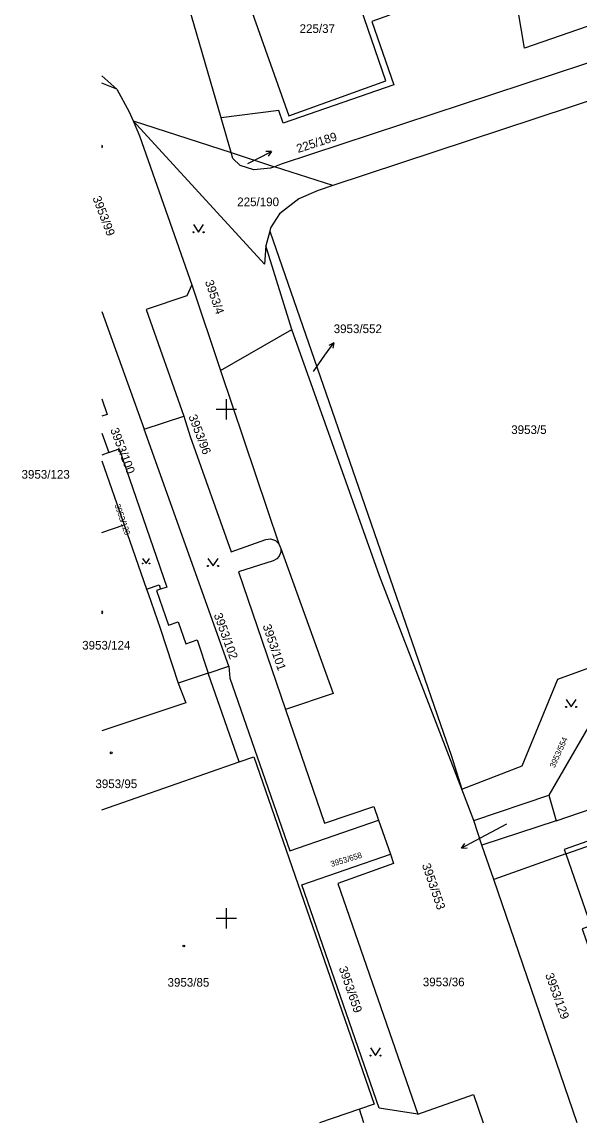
# Model space of a CAD drawing. Extents: x -599970 to -599524, y -1154772 to -1154457.
# Drawn here: x -599970.1 to -599915.3, y -1154770.1 to -1154661.9 of the extents above; entities that cross this region are included whole.
import ezdxf

# ---------------------------------------------------------------- set-up
doc = ezdxf.new("R2010")
doc.units = 0
doc.layers.add('Z-KATASTRALNI MAPA', color=7, linetype='Continuous')
doc.layers.add('Z-KRIZKY CTVERCOVE SITE', color=7, linetype='Continuous')

msp = doc.modelspace()

# ---------------------------------------------------------------- linework, layer by layer
at = {"layer": 'Z-KATASTRALNI MAPA'}
for p, q in [((-599934.32, -1154667.72), (-599940.18, -1154650.81)), ((-599950.09, -1154653.66), (-599943.86, -1154671.15)), ((-599950.53, -1154671.34), (-599955.15, -1154655.41)), ((-599960.77, -1154668.53), (-599962.24, -1154667.94)), ((-599943.86, -1154671.15), (-599934.32, -1154667.72)), ((-599912.85, -1154669.18), (-599939.53, -1154678.01)), ((-599946.25, -1154685.72), (-599959.17, -1154671.63)), ((-599959.17, -1154671.63), (-599958.54, -1154673.12)), ((-599959.17, -1154671.63), (-599949.55, -1154674.76)), ((-599949.55, -1154674.76), (-599950.53, -1154671.34)), ((-599958.54, -1154673.12), (-599953.41, -1154687.76)), ((-599962.24, -1154674.07), (-599962.24, -1154674.27)), ((-599949.55, -1154674.76), (-599945.27, -1154676.15)), ((-599946.9, -1154675.34), (-599945.56, -1154674.66)), ((-599945.56, -1154674.66), (-599946.12, -1154674.66)), ((-599945.56, -1154674.66), (-599945.9, -1154675.11)), ((-599947.89, -1154675.83), (-599946.9, -1154675.34)), ((-599939.53, -1154678.01), (-599945.27, -1154676.15)), ((-599939.53, -1154678.01), (-599940.98, -1154678.49)), ((-599945.75, -1154682.48), (-599946.12, -1154683.94)), ((-599945.67, -1154682.15), (-599945.75, -1154682.48)), ((-599945.75, -1154682.48), (-599945.42, -1154683.44)), ((-599946.12, -1154683.94), (-599946.25, -1154685.72)), ((-599943.58, -1154692.13), (-599946.12, -1154683.94)), ((-599953.41, -1154687.76), (-599950.58, -1154696.17)), ((-599962.24, -1154690.37), (-599958.1, -1154701.93)), ((-599950.58, -1154696.17), (-599943.58, -1154692.13)), ((-599940.32, -1154694.67), (-599939.46, -1154693.44)), ((-599939.46, -1154693.44), (-599939.95, -1154693.71)), ((-599939.46, -1154693.44), (-599939.54, -1154693.99)), ((-599941.45, -1154696.28), (-599940.32, -1154694.67)), ((-599950.58, -1154696.17), (-599944.84, -1154713.2)), ((-599958.1, -1154701.93), (-599954.2, -1154700.66)), ((-599949.75, -1154725.21), (-599958.1, -1154701.93)), ((-599962.24, -1154712.08), (-599960.06, -1154711.32)), ((-599944.84, -1154713.2), (-599944.66, -1154713.65)), ((-599957.86, -1154717.66), (-599957.71, -1154718.09)), ((-599957.71, -1154718.09), (-599956.53, -1154721.49)), ((-599962.24, -1154719.78), (-599962.24, -1154720.08)), ((-599956.53, -1154721.49), (-599954.73, -1154726.88)), ((-599951.8, -1154725.9), (-599949.75, -1154725.21)), ((-599949.75, -1154725.21), (-599949.67, -1154726.39)), ((-599948.75, -1154734.63), (-599951.8, -1154725.9)), ((-599944.21, -1154729.49), (-599940.36, -1154740.65)), ((-599948.75, -1154734.63), (-599947.31, -1154734.14)), ((-599927.92, -1154733.97), (-599926.88, -1154737.29)), ((-599962.24, -1154739.32), (-599948.75, -1154734.63)), ((-599917.6, -1154740.42), (-599906.02, -1154736.47)), ((-599925.69, -1154740.37), (-599926.88, -1154737.29)), ((-599925.69, -1154740.37), (-599918.31, -1154737.91)), ((-599918.31, -1154737.91), (-599917.6, -1154740.42)), ((-599905.63, -1154739.27), (-599916.8, -1154743.23)), ((-599935.06, -1154740.36), (-599933.89, -1154743.69)), ((-599924.89, -1154742.8), (-599925.69, -1154740.37)), ((-599922.48, -1154740.74), (-599925.57, -1154742.39)), ((-599917.6, -1154740.42), (-599924.89, -1154742.8)), ((-599916.65, -1154743.66), (-599905.91, -1154739.85)), ((-599925.57, -1154742.39), (-599926.9, -1154743.09)), ((-599926.9, -1154743.09), (-599926.57, -1154742.64)), ((-599923.73, -1154746.17), (-599924.89, -1154742.8)), ((-599926.9, -1154743.09), (-599926.33, -1154743.08)), ((-599916.65, -1154743.66), (-599923.73, -1154746.17)), ((-599916.8, -1154743.23), (-599916.65, -1154743.66)), ((-599915.52, -1154770.1), (-599923.73, -1154746.17))]:
    msp.add_line(p, q, dxfattribs=at)
for points in [[(-599910.57, -1154658.56), (-599910.18, -1154660.87), (-599920.69, -1154664.5), (-599927.36, -1154625.26), (-599920.83, -1154624.14)], [(-599939.62, -1154650.61), (-599937.98, -1154655.34), (-599936.22, -1154654.73), (-599933.96, -1154661.27), (-599935.72, -1154661.87), (-599933.56, -1154668.1), (-599944.42, -1154671.87), (-599944.85, -1154670.62), (-599950.53, -1154671.34)], [(-599879.03, -1154654.26), (-599944.63, -1154675.91), (-599945.27, -1154676.15)], [(-599962.24, -1154667.21), (-599960.77, -1154668.53)], [(-599960.77, -1154668.53), (-599959.55, -1154670.75), (-599959.17, -1154671.63)], [(-599945.27, -1154676.15), (-599945.68, -1154676.3), (-599947.32, -1154676.45), (-599948.66, -1154676.03), (-599949.38, -1154675.34), (-599949.55, -1154674.76)], [(-599940.98, -1154678.49), (-599942.87, -1154679.31), (-599944.8, -1154680.79), (-599945.67, -1154682.15)], [(-599953.24, -1154681.84), (-599952.74, -1154682.59), (-599952.24, -1154681.84)], [(-599945.42, -1154683.44), (-599937.01, -1154707.62), (-599928.68, -1154731.8), (-599927.92, -1154733.97)], [(-599953.41, -1154687.76), (-599953.9, -1154688.85), (-599957.89, -1154690.19), (-599954.2, -1154700.66)], [(-599926.88, -1154737.29), (-599934.96, -1154716.35), (-599943.58, -1154692.13)], [(-599962.24, -1154698.95), (-599961.72, -1154700.48), (-599962.24, -1154700.66)], [(-599954.2, -1154700.66), (-599953.57, -1154702.65), (-599949.53, -1154713.98), (-599946.13, -1154712.79), (-599945.66, -1154712.72), (-599945.19, -1154712.87), (-599944.84, -1154713.2)], [(-599962.24, -1154702.32), (-599961.57, -1154704.24)], [(-599961.57, -1154704.24), (-599960.53, -1154703.88), (-599955.87, -1154717.45), (-599956.47, -1154717.66)], [(-599961.57, -1154704.24), (-599962.24, -1154704.48)], [(-599962.24, -1154705.05), (-599960.06, -1154711.32)], [(-599960.06, -1154711.32), (-599957.86, -1154717.66), (-599956.62, -1154717.23), (-599956.47, -1154717.66)], [(-599944.66, -1154713.65), (-599944.66, -1154714.03), (-599944.81, -1154714.4), (-599945.06, -1154714.69), (-599945.4, -1154714.87), (-599948.81, -1154715.95), (-599944.21, -1154729.49)], [(-599944.66, -1154713.65), (-599939.5, -1154727.9), (-599944.21, -1154729.49)], [(-599958.24, -1154714.64), (-599957.9, -1154715.14), (-599957.57, -1154714.64)], [(-599951.82, -1154714.63), (-599951.32, -1154715.38), (-599950.82, -1154714.63)], [(-599956.47, -1154717.66), (-599956.86, -1154717.79), (-599955.68, -1154721.2), (-599954.74, -1154720.87), (-599953.99, -1154723.02), (-599952.89, -1154722.65), (-599951.8, -1154725.9)], [(-599926.88, -1154737.29), (-599920.92, -1154735.02), (-599917.44, -1154726.5), (-599897.83, -1154719.36)], [(-599951.8, -1154725.9), (-599954.73, -1154726.88), (-599953.98, -1154728.83), (-599962.24, -1154731.56)], [(-599949.67, -1154726.39), (-599943.76, -1154743.37), (-599935.06, -1154740.36)], [(-599909.19, -1154727.43), (-599913.05, -1154728.79), (-599918.31, -1154737.91)], [(-599916.62, -1154728.48), (-599916.12, -1154729.23), (-599915.62, -1154728.48)], [(-599947.31, -1154734.14), (-599935.49, -1154768.25), (-599936.91, -1154768.74)], [(-599940.36, -1154740.65), (-599935.52, -1154739), (-599935.06, -1154740.36)], [(-599931.19, -1154769.25), (-599934.99, -1154768.64), (-599942.59, -1154746.71), (-599933.89, -1154743.69)], [(-599933.89, -1154743.69), (-599933.58, -1154744.62), (-599939.06, -1154746.56), (-599931.19, -1154769.25)], [(-599916.65, -1154743.66), (-599914.2, -1154750.72), (-599915.05, -1154751.02), (-599913.82, -1154754.56), (-599912.66, -1154757.92)], [(-599935.85, -1154762.73), (-599935.35, -1154763.48), (-599934.85, -1154762.73)], [(-599931.19, -1154769.25), (-599925.73, -1154767.31), (-599924.76, -1154770.1)], [(-599936.91, -1154768.74), (-599940.86, -1154770.1)], [(-599936.49, -1154770.1), (-599936.91, -1154768.74)]]:
    msp.add_lwpolyline(points, dxfattribs=at)
for centre, radius in [((-599953.24, -1154682.59), 0.05), ((-599952.24, -1154682.59), 0.05), ((-599958.24, -1154715.14), 0.0335), ((-599957.57, -1154715.14), 0.0335), ((-599951.82, -1154715.38), 0.05), ((-599950.82, -1154715.38), 0.05), ((-599916.62, -1154729.23), 0.05), ((-599915.62, -1154729.23), 0.05), ((-599961.32, -1154733.74), 0.0875), ((-599954.2, -1154752.71), 0.0875), ((-599935.85, -1154763.48), 0.05), ((-599934.85, -1154763.48), 0.05)]:
    msp.add_circle(centre, radius, dxfattribs=at)
for centre, radius, start, end in [((-599962.28, -1154674.17), 0.106, 290.0127, 69.9873), ((-599962.34, -1154719.93), 0.183, 304.9298, 55.0702)]:
    msp.add_arc(centre, radius, start, end, dxfattribs=at)
at = {"layer": 'Z-KRIZKY CTVERCOVE SITE'}
for p, q in [((-599950, -1154701), (-599950, -1154699)), ((-599949, -1154700), (-599951, -1154700)), ((-599950, -1154751), (-599950, -1154749)), ((-599949, -1154750), (-599951, -1154750))]:
    msp.add_line(p, q, dxfattribs=at)

# ---------------------------------------------------------------- texts
at = {"layer": 'Z-KATASTRALNI MAPA'}
for s, p in [('225/37', (-599942.81, -1154663.01)), ('225/190', (-599948.94, -1154680.03)), ('3953/552', (-599939.46, -1154692.5)), ('3953/5', (-599922.01, -1154702.41)), ('3953/123', (-599970.14, -1154706.8)), ('3953/124', (-599964.18, -1154723.59)), ('3953/95', (-599962.88, -1154737.2)), ('3953/85', (-599955.79, -1154756.71)), ('3953/36', (-599930.7, -1154756.67))]:
    msp.add_text(s, height=0.85, dxfattribs=at).set_placement(p)
for s, height, rotation, p in [('225/189', 0.85, 18, (-599942.96, -1154674.81)), ('3953/99', 0.85, 291, (-599963.18, -1154679.22)), ('3953/4', 0.85, 289, (-599952.13, -1154687.45)), ('3953/96', 0.85, 291, (-599953.75, -1154700.68)), ('3953/100', 0.85, 291, (-599961.44, -1154701.99)), ('3953/120', 0.57, 289, (-599961, -1154709.4)), ('3953/102', 0.85, 290, (-599951.26, -1154720.18)), ('3953/101', 0.85, 289, (-599946.46, -1154721.26)), ('3953/554', 0.57, 66, (-599917.74, -1154735.26)), ('3953/658', 0.57, 17, (-599939.67, -1154744.95)), ('3953/553', 0.85, 289, (-599930.8, -1154744.75)), ('3953/659', 0.85, 289, (-599938.97, -1154754.88)), ('3953/129', 0.85, 290, (-599918.69, -1154755.54))]:
    msp.add_text(s, height=height, rotation=rotation, dxfattribs=at).set_placement(p)

doc.saveas('drawing.dxf')
